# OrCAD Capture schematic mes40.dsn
size A
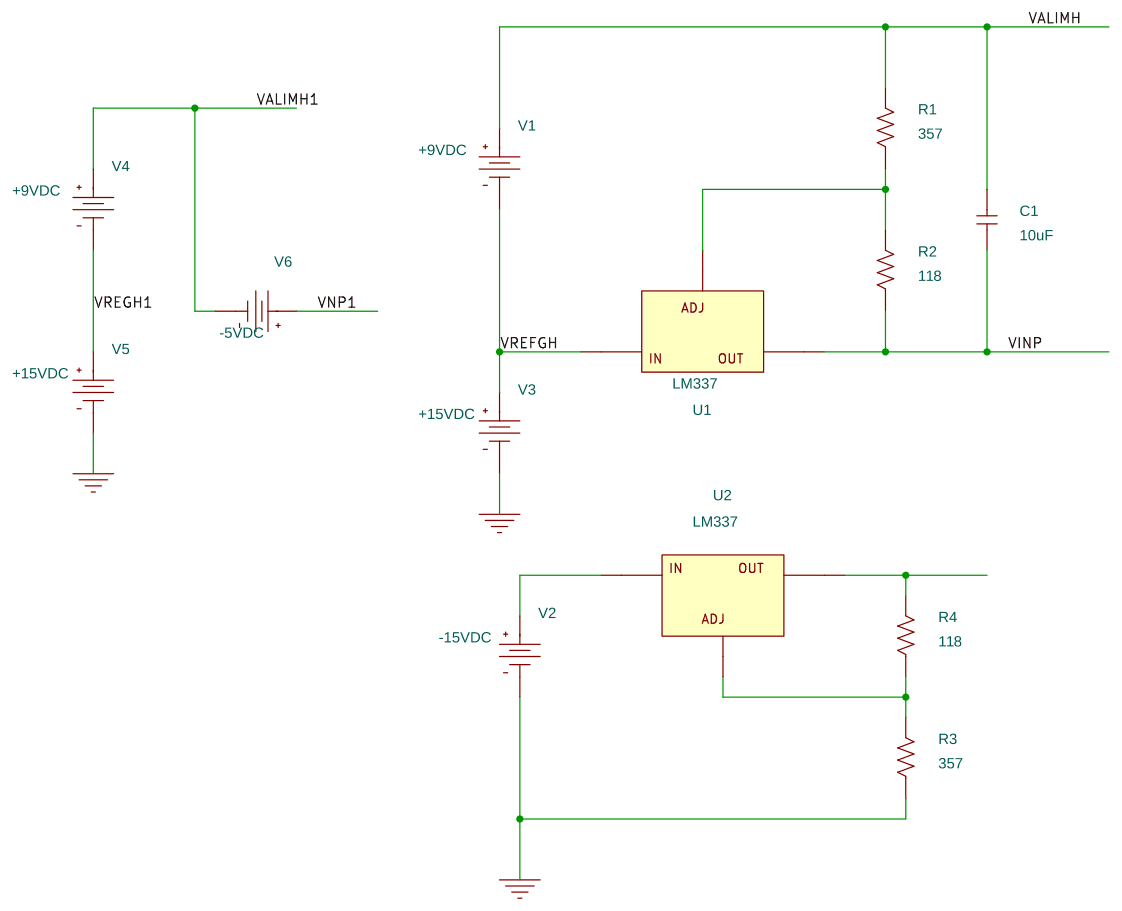
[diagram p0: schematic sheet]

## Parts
C1  10uF  [cap196]
R1  357  [AXRC05]
R2  118  [AXRC05]
R3  357  [AXRC05]
R4  118  [AXRC05]
U1  LM337
U2  LM337
V1  VDC
V2  VDC
V3  VDC
V4  VDC
V5  VDC
V6  VDC

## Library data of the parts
C1 = C
R1-R4 = R
U1 = LM337_1
U2 = LM337
V1 V4 = VDC: DC: +9VDC
V2 = VDC: DC: -15VDC
V3 V5 = VDC: DC: +15VDC
V6 = VDC: DC: -5VDC

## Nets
VINP: C1.1 R2.1 U1.OUT
0: R3.1 V2.1(-) V3.1(-) V5.1(-)
VALIMH: C1.2 R1.2 V1.0(+)
VALIMH1: V4.0(+) V6.1(-)
VNP1: V6.0(+)
VREFGH: U1.IN V1.1(-) V3.0(+)
VREGH1: V4.1(-) V5.0(+)
N14438: R1.1 R2.2 U1.ADJ
N15099: U2.IN V2.0(+)
N15154: R4.2 U2.OUT
N15161: R3.2 R4.1 U2.ADJ
